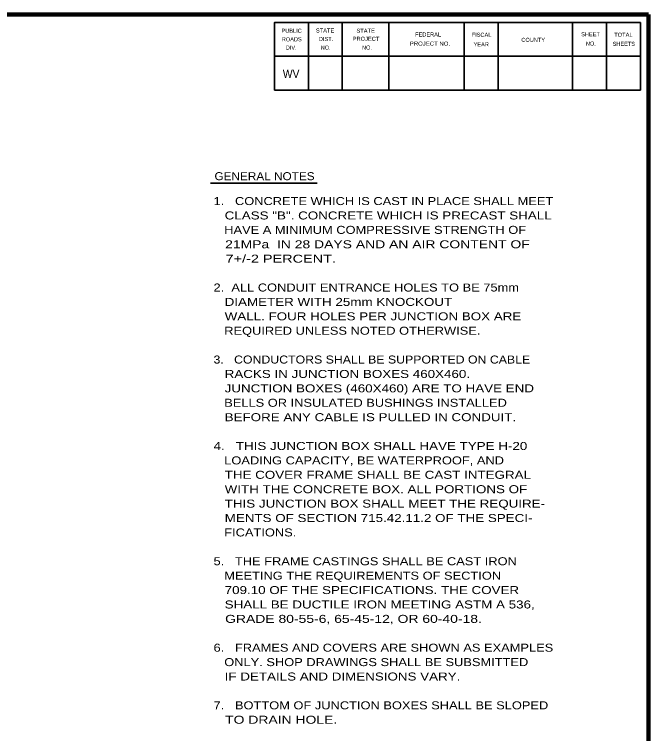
# Model space of a CAD drawing. Extents: x 918 to 1774, y -8 to 536.
# Drawn here: x 1529.3 to 1767, y 260.3 to 529.8 of the extents above; entities that cross this region are included whole.
import ezdxf

# ---------------------------------------------------------------- set-up
doc = ezdxf.new("R2010")
doc.units = 0
doc.header["$LTSCALE"] = 1.2
doc.layers.add('1', color=7, linetype='Continuous', lineweight=35)
doc.layers.add('61', color=7, linetype='Continuous', lineweight=35)

msp = doc.modelspace()

# ---------------------------------------------------------------- linework, layer by layer
at = {"layer": '1', "lineweight": 158}
msp.add_line((1766.999, 3.718), (1766.999, 529.818), dxfattribs=at)
at = {"layer": '1', "lineweight": 13}
msp.add_line((1766.999, 3.718), (1766.999, 529.818), dxfattribs=at)
at = {"layer": '1'}
msp.add_line((1602.819, 466.617), (1642.779, 466.617), dxfattribs=at)
at = {"layer": '1', "lineweight": 158}
msp.add_lwpolyline([(1766.999, 529.818), (975.299, 529.718), (975.399, 3.718)], dxfattribs=at)
at = {"layer": '61'}
for p, q in [((1639.499, 526.818), (1639.499, 501.418)), ((1652.199, 526.818), (1652.199, 501.418)), ((1669.599, 526.818), (1669.599, 501.418)), ((1697.899, 526.818), (1697.899, 501.418)), ((1710.599, 526.818), (1710.599, 501.418)), ((1738.499, 526.818), (1738.499, 501.418)), ((1751.199, 526.818), (1751.199, 501.418)), ((1763.899, 514.118), (1626.799, 514.118))]:
    msp.add_line(p, q, dxfattribs=at)
for points in [[(1763.899, 526.818), (1626.799, 526.818), (1626.799, 501.418)], [(1763.899, 526.818), (1763.899, 501.418), (1626.799, 501.418)]]:
    msp.add_lwpolyline(points, dxfattribs=at)

# ---------------------------------------------------------------- texts
at = {"layer": '1'}
for s, height, width, p in [('WV', 3.048, 0.95, (1629.899, 506.018)), ('GENERAL NOTES', 3, 1.1, (1604.291, 467.669)), ('1.   CONCRETE WHICH IS CAST IN PLACE SHALL MEET', 3, 1.2, (1603.931, 458.355)), ('   CLASS "B". CONCRETE WHICH IS PRECAST SHALL', 3, 1.25, (1603.931, 452.955)), ('   HAVE A MINIMUM COMPRESSIVE STRENGTH OF', 3, 1.2, (1603.931, 447.555)), ('   21MPa  IN 28 DAYS AND AN AIR CONTENT OF', 3, 1.3, (1603.931, 442.155)), ('   7+/-2 PERCENT.', 3, 1.35, (1603.931, 436.755)), ('2.  ALL CONDUIT ENTRANCE HOLES TO BE 75mm', 3, 1.2, (1603.931, 425.955)), ('   DIAMETER WITH 25mm KNOCKOUT', 3, 1.25, (1603.931, 420.555)), ('   WALL. FOUR HOLES PER JUNCTION BOX ARE', 3, 1.25, (1603.931, 415.155)), ('   REQUIRED UNLESS NOTED OTHERWISE.', 3, 1.2, (1603.931, 409.755)), ('3.   CONDUCTORS SHALL BE SUPPORTED ON CABLE', 3, 1.15, (1603.931, 398.955)), ('   RACKS IN JUNCTION BOXES 460X460.', 3, 1.25, (1603.931, 393.555)), ('   JUNCTION BOXES (460X460) ARE TO HAVE END', 3, 1.25, (1603.931, 388.155)), ('   BELLS OR INSULATED BUSHINGS INSTALLED', 3, 1.2, (1603.931, 382.755)), ('   BEFORE ANY CABLE IS PULLED IN CONDUIT.', 3, 1.25, (1603.931, 377.355)), ('4.   THIS JUNCTION BOX SHALL HAVE TYPE H-20', 3, 1.25, (1603.931, 366.555)), ('   LOADING CAPACITY, BE WATERPROOF, AND', 3, 1.2, (1603.931, 361.155)), ('   THE COVER FRAME SHALL BE CAST INTEGRAL', 3, 1.25, (1603.931, 355.755)), ('   WITH THE CONCRETE BOX. ALL PORTIONS OF', 3, 1.25, (1603.931, 350.355)), ('   THIS JUNCTION BOX SHALL MEET THE REQUIRE-', 3, 1.25, (1603.931, 344.955)), ('   MENTS OF SECTION 715.42.11.2 OF THE SPECI-', 3, 1.25, (1603.931, 339.555)), ('   FICATIONS.', 3, 1.2, (1603.931, 334.155)), ('5.   THE FRAME CASTINGS SHALL BE CAST IRON', 3, 1.2, (1603.931, 323.355)), ('   MEETING THE REQUIREMENTS OF SECTION', 3, 1.2, (1603.931, 317.955)), ('   709.10 OF THE SPECIFICATIONS. THE COVER', 3, 1.25, (1603.931, 312.555)), ('   SHALL BE DUCTILE IRON MEETING ASTM A 536,', 3, 1.25, (1603.931, 307.155)), ('   GRADE 80-55-6, 65-45-12, OR 60-40-18.', 3, 1.3, (1603.931, 301.755)), ('6.   FRAMES AND COVERS ARE SHOWN AS EXAMPLES', 3, 1.2, (1603.931, 290.955)), ('   ONLY. SHOP DRAWINGS SHALL BE SUBSMITTED', 3, 1.2, (1603.931, 285.555)), ('   IF DETAILS AND DIMENSIONS VARY.', 3, 1.25, (1603.931, 280.155)), ('7.   BOTTOM OF JUNCTION BOXES SHALL BE SLOPED', 3, 1.2, (1603.931, 269.355)), ('   TO DRAIN HOLE.', 3, 1.3, (1603.931, 263.955))]:
    msp.add_text(s, height=height, dxfattribs=dict(at, width=width)).set_placement(p)
at = {"layer": '61'}
for s, height, rotation, p in [('PUBLIC', 1.525, 0.033, (1629.399, 522.918)), ('FEDERAL', 1.523, 0.007, (1679.499, 521.518)), ('FISCAL', 1.525, 359.942, (1700.699, 521.418)), ('SHEET', 1.525, 0.059, (1741.699, 521.618)), ('ROADS', 1.525, 0.124, (1629.499, 519.718)), ('DIST.', 1.525, 0.056, (1643.399, 519.818)), ('COUNTY', 1.523, 0.069, (1719.299, 519.518)), ('DIV.', 1.525, 359.932, (1630.999, 516.618)), ('YEAR', 1.523, 0.105, (1701.399, 517.818)), ('SHEETS', 1.523, 359.959, (1753.499, 518.018))]:
    msp.add_text(s, height=height, rotation=rotation, dxfattribs=at).set_placement(p)
for s, rotation, width, p in [('STATE', 0.059, 1.05, (1642.299, 523.018)), ('STATE', 0.059, 1.05, (1657.499, 522.918)), ('TOTAL', 359.926, 1.05, (1754.099, 521.418)), ('PROJECT', 359.908, 1.05, (1656.099, 519.918)), ('NO.', 359.852, 0.9, (1644.099, 516.618)), ('NO.', 0.225, 0.9, (1659.599, 516.618)), ('PROJECT NO.', 359.922, 1.1, (1677.499, 518.118)), ('NO.', 359.852, 0.9, (1743.499, 518.118))]:
    msp.add_text(s, height=1.525, rotation=rotation, dxfattribs=dict(at, width=width)).set_placement(p)

doc.saveas('drawing.dxf')
